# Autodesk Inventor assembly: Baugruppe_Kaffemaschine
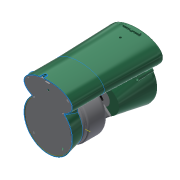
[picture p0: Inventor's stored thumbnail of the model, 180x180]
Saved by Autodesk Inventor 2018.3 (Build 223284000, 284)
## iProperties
Created: 2019-01
Part Number: Baugruppe_Kaffemaschine
Material: Generisch
Document SubType Name: Assembly
Designer: zand
Title: KAFFEEMASCHINE1_ZAND_ASM
Sending System: CREO PARAMETRIC BY PTC INC, 2018100
Preprocessor: CREO PARAMETRIC BY PTC INC, 2018100
Author: zand
Revision Number: 44LAST_VERSION
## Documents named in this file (17)
- D:\10_CAD-ÜBUNGEN\KAFFEEMASCHINE\Workspaces\Arbeitsbereich\Baugruppe_Kaffemaschine.iam
- D:\10_CAD-ÜBUNGEN\KAFFEEMASCHINE\Workspaces\Arbeitsbereich\WASSERTANK_ZAND_AF0.ipt
- D:\10_CAD-ÜBUNGEN\KAFFEEMASCHINE\Workspaces\Arbeitsbereich\WASSERTANKDECKEL_ZAND.ipt
- D:\10_CAD-ÜBUNGEN\KAFFEEMASCHINE\Workspaces\Arbeitsbereich\WASSERAUSLASSDECKEL_ZAND.ipt
- D:\10_CAD-ÜBUNGEN\KAFFEEMASCHINE\Workspaces\Arbeitsbereich\ABSTELLFLCHE_ZAND0.ipt
- D:\10_CAD-ÜBUNGEN\KAFFEEMASCHINE\Workspaces\Arbeitsbereich\GEHAEUSE-FILTERKAMMER_ZAND.ipt
- D:\10_CAD-ÜBUNGEN\KAFFEEMASCHINE\Workspaces\Arbeitsbereich\BAUGRUPPE_GLASSKANNE_ERFANIAN_ASM.iam
- D:\10_CAD-ÜBUNGEN\KAFFEEMASCHINE\Workspaces\Arbeitsbereich\FILTERKAMMER_ZAND.ipt
- D:\10_CAD-ÜBUNGEN\KAFFEEMASCHINE\Workspaces\Arbeitsbereich\DURCHLASS_ERFANIAN.ipt
- D:\10_CAD-ÜBUNGEN\KAFFEEMASCHINE\Workspaces\Arbeitsbereich\UNTERPLATTE_ZAND.ipt
- D:\10_CAD-ÜBUNGEN\KAFFEEMASCHINE\Workspaces\Arbeitsbereich\WASSERDURCHLASS_ERFANIAN_ASM.iam
- D:\10_CAD-ÜBUNGEN\KAFFEEMASCHINE\Workspaces\Arbeitsbereich\SHALTER_ERFANIAN_ASM.iam
- D:\10_CAD-ÜBUNGEN\KAFFEEMASCHINE\Workspaces\Arbeitsbereich\DICHTUNG-DURCHLASS_ZAND.ipt
- D:\10_CAD-ÜBUNGEN\KAFFEEMASCHINE\Workspaces\Arbeitsbereich\BLACKBOX_ZAND.ipt
- D:\10_CAD-ÜBUNGEN\KAFFEEMASCHINE\Workspaces\Arbeitsbereich\SCHLAUCH_ZAND.ipt
- D:\10_CAD-ÜBUNGEN\KAFFEEMASCHINE\Workspaces\Arbeitsbereich\Spiralfeder Auslass.ipt
- D:\10_CAD-ÜBUNGEN\KAFFEEMASCHINE\Workspaces\Arbeitsbereich\Sprengring Kanne.ipt
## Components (16 placed, 16 different names)
1. Wasstank
2. Wassertankdeckel
3. Wasserauslassdeckel
4. Abstellflaeche
5. Filterkammergehaeuse
6. Baugruppe_Glaskanne [sub-assembly] — Passend:8, Passend:9
7. Fiterkammer
8. Durchlass — Passend:5
9. Unterplatte
10. Baugruppe_Wasserdurchlass [sub-assembly]
11. Baugruppe_Schalter [sub-assembly]
12. Dichtung-Durchlass
13. Blackbox
14. Schlauch
15. Spiralfeder Auslass:1 — Passend:5
16. Sprengring Kanne:1 — Passend:8, Passend:9
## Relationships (3: Mate 3)
- Passend:5 [Mate]: Durchlass ↔ Spiralfeder Auslass:1
- Passend:8 [Mate]: Baugruppe_Glaskanne ↔ Sprengring Kanne:1
- Passend:9 [Mate]: Baugruppe_Glaskanne ↔ Sprengring Kanne:1
